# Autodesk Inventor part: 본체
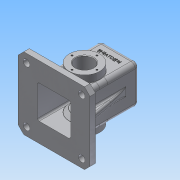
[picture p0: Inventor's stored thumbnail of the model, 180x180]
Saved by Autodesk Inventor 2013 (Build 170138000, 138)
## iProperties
Created: 2016-02
Part Number: 본체
Material: 알루미늄 6061
Document SubType Name: Modeling
Designer: Administrator
Density: 2.71 g/cm^3
Mass: 933.487 g
Surface Area: 1043.49 cm^2
Volume: 344.46 cm^3
Author: Administrator
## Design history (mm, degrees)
sketch "스케치1"
  geometry: L1 (35, -35)-(-35, -35); L2 (-35, -35)-(-35, 35); L3 (-35, 35)-(35, 35); L4 (35, 35)-(35, -35); L5 (35, -35)-(-35, 35); L6 (-35, -35)-(35, 35); 1 further point
  constraints: 12 end point, 2 midpoint, 2 parallel, 1 horizontal, 1 perpendicular
  dimensions: "d0" = 70 distance of L2.end L3.end; "d1" = 70 distance of L1.end L2.end
extrude "돌출1" new body sketch "스케치1" distance "d2" = 120; taper "d3" = 0 deg
feature "쉘1" dims "d29" = 5
sketch "스케치3"
  geometry: C1 r 27.5 at (0, 55); 1 further point
  constraints: 1 centre point, 1 vertical alignment
  dimensions: "d7" = 55 diameter of C1; "d8" = 55 distance of point (0, 0) C1.centre
extrude "돌출2" join sketch "스케치3" stored distance "d9" = 96; taper "d10" = 0 deg
sketch "스케치4"
  geometry: C1 r 20 at (0, 0); 1 further point
  constraints: 1 centre point, 1 coincident
  dimensions: "d11" = 40 diameter of C1
extrude "돌출3" join sketch "스케치4" distance "d12" = 10; taper "d13" = -10 deg
sketch "스케치5"
  geometry: L1 (-35, 35)-(-35, -35) reference; L2 (-35, -35)-(35, -35) reference; L3 (35, -35)-(35, 35) reference; L4 (35, 35)-(-35, 35) reference; L5 (-65, -65)-(65, -65); L6 (65, -65)-(65, 65); L7 (65, 65)-(-65, 65); L8 (-65, 65)-(-65, -65); L9 (-65, -65)-(65, 65); L10 (65, -65)-(-65, 65); A1 r 8 centre (-27, 27) between (-27, 35) and (-35, 27) reference; A2 r 8 centre (-27, -27) between (-35, -27) and (-27, -35) reference; A3 r 8 centre (27, -27) between (27, -35) and (35, -27) reference; A4 r 8 centre (27, 27) between (35, 27) and (27, 35) reference; 1 further point
  constraints: 12 end point, 2 midpoint, 2 parallel, 1 horizontal, 1 perpendicular
  dimensions: "d14" = 130 distance of L7.end L6.end; "d15" = 130 distance of L6.end L5.end
extrude "돌출4" join sketch "스케치5" distance "d16" = 10; taper "d17" = 0 deg
chamfer "모따기1" distance "d18" = 10; stored, may be unused: second distance "d19" = 2, angle "d20" = 45 deg
sketch "스케치6"
  geometry: L1 (35, 120)-(35, 10) reference; L2 (35, 10)-(65, 10) reference; L3 (65, 10)-(65, 0) reference; L4 (65, 0)-(30, 0) reference; L5 (-65, 0)-(-65, 10) reference; L6 (-65, 10)-(-35, 10) reference; L7 (-35, 10)-(-35, 120) reference; L8 (-35, 120)-(-20, 120) reference; L9 (-20, 120)-(-18.237, 130) reference; L10 (-18.237, 130)-(18.237, 130) reference; L11 (18.237, 130)-(20, 120) reference; L12 (20, 120)-(35, 120) reference; L13 (50, 10)-(35, 95.069); L14 (30, 0)-(30, 115) reference; L15 (-30, 115)-(-30, 0) reference; L16 (-30, 0)-(-65, 0) reference; L17 (30, 115)-(-30, 115) reference; C1 r 27.5 at (0, 55) reference; 1 further point
  constraints: 2 end point, 1 midpoint, 1 point on line
  dimensions: "d21" = 15 distance of L2.end L13.start; "d22" = 10 deg angle of L13 L3
feature "리브1" sketch "스케치6" dims "d23" = 1, "d24" = 10, "d25" = 0, "d26" = 0, "d27" = 1, "d28" = 1
extrude "돌출5" cut sketch "스케치3" stored distance "d30" = 60; taper "d31" = 0 deg
hole "구멍1" diameter "d37" = 21; stored, may be unused: countersink angle "d41" = 90 deg, drill point angle "d43" = 118 deg; dims "d35" = 10, "d36" = 10, "d38" = 6, "d39" = 28, "d40" = 4, "d42" = 8
sketch "스케치8"
  geometry: C1 r 27.5 at (27, 55); A1 r 27.5 centre (27, 55) between (0, 60.22) and (0, 49.78) reference; 1 further point
  constraints: 1 centre point, 1 coincident
  dimensions: "d44" = 55 diameter of C1
extrude "돌출7" join sketch "스케치8" distance "d45" = 7; taper "d46" = -45 deg
sketch "스케치7"
  geometry: C1 r 27.5 at (0, 0) reference; C2 r 16 at (0, 0); 1 further point
  constraints: 1 centre point, 1 coincident
  dimensions: "d32" = 32 diameter of C2
extrude "돌출6" cut sketch "스케치7" stored distance "d33" = 60; taper "d34" = 0 deg
sketch "스케치9"
  geometry: C1 r 16 at (0, 0) reference; 2 further points
  constraints: 1 vertical alignment
  dimensions: "d47" = 22.5 distance of C1.centre point (0, 22.5)
hole "구멍2" sketch "스케치9" at (0, 22.5) diameter "d48" = 3.242; stored, may be unused: countersink angle "d52" = 90 deg, drill point angle "d54" = 118 deg; dims "d49" = 8, "d50" = 28, "d51" = 4, "d53" = 10
fillet "모깎기3" dims "d58" = 0.5
chamfer "모따기2" distance "d59" = 1; stored, may be unused: second distance "d60" = 2, angle "d61" = 45 deg
sketch "스케치10"
  geometry: L1 (65, -55)-(65, 55) reference; L2 (55, 65)-(-55, 65) reference; 2 further points
  dimensions: "d62" = 15 distance from line of point (50, 50) L1; "d63" = 15 distance from line of point (50, 50) L2
hole "구멍3" sketch "스케치10" at (50, 50) diameter "d64" = 12; stored, may be unused: countersink angle "d68" = 90 deg, drill point angle "d70" = 118 deg; dims "d65" = 8, "d66" = 28, "d67" = 4, "d69" = 10
fillet "모깎기4" dims "d77" = 3
fillet "모깎기5" dims "d78" = 0.5
fillet "모깎기6" dims "d79" = 8
fillet "모깎기7" dims "d80" = 8
fillet "모깎기8" dims "d81" = 3
fillet "모깎기9" dims "d82" = 3
fillet "모깎기10" dims "d83" = 3
fillet "모깎기11" dims "d84" = 3
sketch "스케치11"
  geometry: L1 (27, 65)-(-27, 65) reference; L2 (35, 7.416)-(35, 57) reference; L3 (-18.237, 75)-(18.237, 75) reference; 2 further points
  constraints: 1 other
  dimensions: "d86" = 35 distance from line of L2 point (0, 45); "d87" = 30 distance from line of L3 point (0, 45)
feature "엠보싱1" sketch "스케치11" dims "d88" = 0.5, "d89" = 0
node "솔리드1"
mirror "대칭1"
mirror "대칭2"
pattern_circular "원형 패턴1" dims angle "d56" = 360 deg
mirror "대칭3"
pattern_linear "직사각형 패턴1" dims "d73" = 100
node "절단 모서리 투영1"
